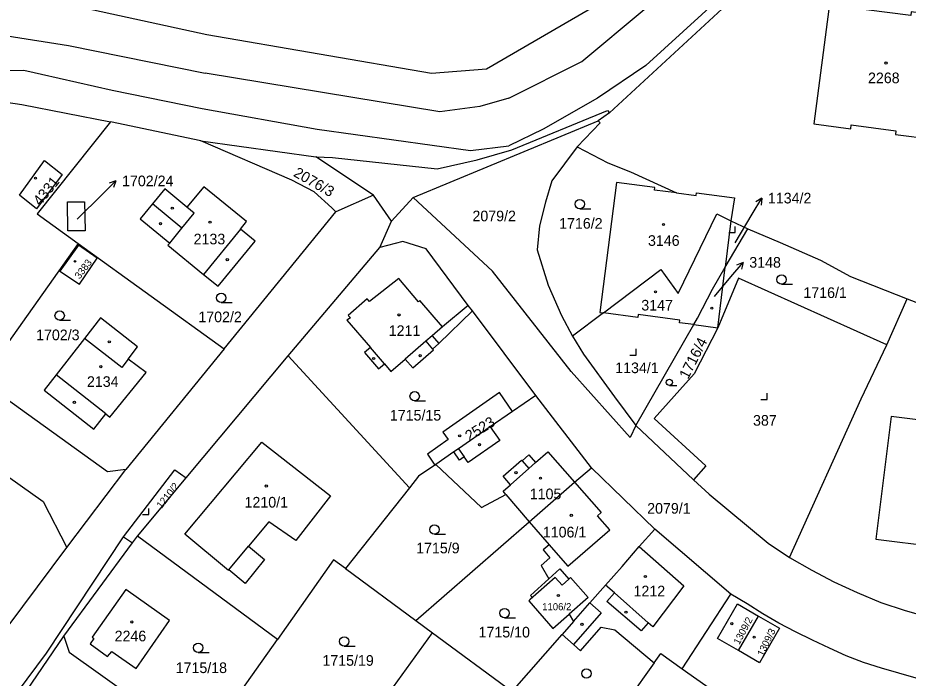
# Model space of a CAD drawing. Extents: x -679220 to -673243, y -1075091 to -1066557.
# Drawn here: x -676919.9 to -676777.4, y -1071850.3 to -1071744.6 of the extents above; entities that cross this region are included whole.
import ezdxf

# ---------------------------------------------------------------- set-up
doc = ezdxf.new("R2010")
doc.units = 0
for name, color, linetype in [('Hranice parcel', 7, 'Continuous'), ('Parcelní čísla', 7, 'Continuous'), ('Pop  PČ popisy', 7, 'Continuous'), ('Vnitřní kresba', 7, 'Continuous'), ('Značky budov', 7, 'Continuous'), ('Značky kultur', 7, 'Continuous')]:
    doc.layers.add(name, color=color, linetype=linetype)

msp = doc.modelspace()

# ---------------------------------------------------------------- linework, layer by layer
at = {"layer": 'Hranice parcel'}
for p, q in [((-676825.22, -1071759.86), (-676827.02, -1071761.13)), ((-676890.63, -1071764.33), (-676905.07, -1071761.28)), ((-676890.63, -1071764.33), (-676872.2, -1071766.9)), ((-676862.96, -1071773.03), (-676872.2, -1071766.9)), ((-676862.96, -1071773.03), (-676869.01, -1071775.7)), ((-676886.88, -1071797.62), (-676869.01, -1071775.7)), ((-676805.78, -1071777.13), (-676806.7, -1071784.54)), ((-676806.7, -1071784.54), (-676803.09, -1071778.39)), ((-676910.26, -1071780.74), (-676925.83, -1071802.72)), ((-676910.26, -1071780.74), (-676886.88, -1071797.62)), ((-676876.64, -1071798.73), (-676861.98, -1071781.43)), ((-676807.9, -1071794.25), (-676806.7, -1071784.54)), ((-676780.82, -1071796.99), (-676777.6, -1071789.6)), ((-676777.6, -1071789.6), (-676770.27, -1071792.52)), ((-676847.15, -1071791.53), (-676847.81, -1071790.66)), ((-676837, -1071805.08), (-676847.15, -1071791.53)), ((-676826.18, -1071791.87), (-676831.15, -1071795.62)), ((-676821, -1071809.91), (-676811.75, -1071793.75)), ((-676811.75, -1071793.75), (-676807.9, -1071794.25)), ((-676886.88, -1071797.62), (-676902.63, -1071816.93)), ((-676892.95, -1071818.26), (-676876.64, -1071798.73)), ((-676876.64, -1071798.73), (-676857.22, -1071819.86)), ((-676837, -1071805.08), (-676840.74, -1071807.66)), ((-676828.1, -1071816.65), (-676837, -1071805.08)), ((-676821, -1071809.91), (-676811.78, -1071818.6)), ((-676912.06, -1071829.42), (-676902.63, -1071816.93)), ((-676853.16, -1071816.22), (-676853, -1071816.11)), ((-676817.95, -1071826.46), (-676828.1, -1071816.65)), ((-676900.76, -1071827.6), (-676892.95, -1071818.26)), ((-676857.22, -1071819.86), (-676867.46, -1071832.8)), ((-676856.2, -1071841.09), (-676838.05, -1071825.29)), ((-676805.82, -1071836.89), (-676817.95, -1071826.46)), ((-676912.53, -1071843.62), (-676901.53, -1071828.65)), ((-676903, -1071827.69), (-676901.53, -1071828.65)), ((-676901.53, -1071828.65), (-676900.76, -1071827.6)), ((-676878.33, -1071844.13), (-676900.76, -1071827.6)), ((-676921.47, -1071842.02), (-676912.06, -1071829.42)), ((-676867.46, -1071832.8), (-676856.2, -1071841.09)), ((-676831.44, -1071834.22), (-676828.63, -1071837.43)), ((-676813.57, -1071848.81), (-676805.82, -1071836.89)), ((-676838.14, -1071837.94), (-676834.3, -1071842.37)), ((-676828.63, -1071837.43), (-676831.68, -1071840.08)), ((-676834.3, -1071842.37), (-676831.68, -1071840.08)), ((-676831.68, -1071840.08), (-676830.99, -1071841.28)), ((-676856.2, -1071841.09), (-676853.52, -1071843.07)), ((-676830.99, -1071841.28), (-676832.82, -1071843.36)), ((-676804.59, -1071845.91), (-676801.39, -1071840.38)), ((-676919.84, -1071854.28), (-676912.53, -1071843.62)), ((-676890.49, -1071861.28), (-676878.33, -1071844.13)), ((-676874.88, -1071872.43), (-676853.52, -1071843.07)), ((-676853.52, -1071843.07), (-676840.79, -1071852.44)), ((-676840.79, -1071852.44), (-676832.82, -1071843.36)), ((-676818.08, -1071847.87), (-676827.91, -1071861.55))]:
    msp.add_line(p, q, dxfattribs=at)
for points in [[(-676751.12, -1071692.06), (-676777.6, -1071716.31), (-676788.46, -1071725.85), (-676825.22, -1071759.86)], [(-677008.25, -1071788.41), (-676995.25, -1071771.16), (-676987.7, -1071761.27), (-676980.12, -1071752.62), (-676972.27, -1071748.26), (-676964.86, -1071744.84), (-676950.01, -1071743.35), (-676935.78, -1071742.14), (-676921.36, -1071742.37), (-676911.47, -1071742.59), (-676889.65, -1071747.32), (-676853.71, -1071753.48), (-676844.92, -1071752.82), (-676823.69, -1071740.46)], [(-676773.55, -1071764.09), (-676771, -1071744.47), (-676776.92, -1071743.7), (-676777, -1071744.29), (-676784.12, -1071743.37), (-676784.04, -1071742.77), (-676789.95, -1071742.01), (-676792.53, -1071761.62), (-676786.59, -1071762.39), (-676786.52, -1071761.79), (-676779.4, -1071762.72), (-676779.47, -1071763.32), (-676773.55, -1071764.09)], [(-676926.82, -1071757.39), (-676919.25, -1071758.51), (-676905.07, -1071761.28)], [(-676872.2, -1071766.9), (-676869.55, -1071767.02), (-676852.79, -1071768.83), (-676846.37, -1071767.4), (-676840.86, -1071765.76), (-676825.55, -1071759.5), (-676825.22, -1071759.86)], [(-676905.07, -1071761.28), (-676916.81, -1071776.01), (-676910.26, -1071780.74)], [(-676821, -1071809.91), (-676821.93, -1071811.81), (-676831.37, -1071801.24), (-676843.92, -1071785.19), (-676856.66, -1071773.41), (-676827.02, -1071761.13)], [(-676827.02, -1071761.13), (-676826.71, -1071761.46), (-676830.41, -1071765.32)], [(-676869.01, -1071775.7), (-676869.67, -1071775.03), (-676872.47, -1071772.52), (-676876.08, -1071770.65), (-676890.63, -1071764.33)], [(-676830.41, -1071765.32), (-676834.45, -1071770.74), (-676835.48, -1071774.13), (-676836.43, -1071777.94), (-676836.78, -1071781.79), (-676835.01, -1071787.45), (-676832.91, -1071792.27), (-676831.15, -1071795.62)], [(-676830.41, -1071765.32), (-676825.51, -1071767.83), (-676821.88, -1071769.29), (-676814.49, -1071772.68)], [(-676912.83, -1071769.72), (-676916.91, -1071775.2), (-676919.66, -1071773.02), (-676915.61, -1071767.47), (-676912.83, -1071769.72)], [(-676900.32, -1071776.84), (-676895.6, -1071780.69), (-676895.88, -1071781.04), (-676890.17, -1071785.7), (-676887.83, -1071787.61), (-676881.94, -1071780.39), (-676884.28, -1071778.48), (-676883.29, -1071777.25), (-676890.12, -1071771.67), (-676892.85, -1071774.94), (-676896.4, -1071772.04), (-676898.36, -1071774.44), (-676900.32, -1071776.84)], [(-676814.49, -1071772.68), (-676818.04, -1071772.22), (-676817.98, -1071771.78), (-676824.08, -1071770.98), (-676826.78, -1071791.79), (-676826.18, -1071791.87)], [(-676861.98, -1071781.43), (-676860.12, -1071777.17), (-676862.96, -1071773.03)], [(-676814.49, -1071772.68), (-676811.34, -1071773.09), (-676811.28, -1071772.64), (-676805.21, -1071773.43), (-676805.78, -1071777.13)], [(-676911.97, -1071774.12), (-676909.25, -1071774.08), (-676909.15, -1071778.76), (-676911.91, -1071778.74), (-676911.97, -1071774.12)], [(-676826.18, -1071791.87), (-676817, -1071784.94), (-676814.22, -1071788.75), (-676808.04, -1071776.02), (-676805.78, -1071777.13)], [(-676805.78, -1071777.13), (-676804.01, -1071778), (-676803.09, -1071778.39)], [(-676803.09, -1071778.39), (-676797.91, -1071780.61), (-676791.43, -1071783.43), (-676786.63, -1071786.04), (-676777.6, -1071789.6)], [(-676910.21, -1071781.01), (-676913.16, -1071785.17), (-676910.06, -1071787.26), (-676907.22, -1071783.1), (-676910.21, -1071781.01)], [(-676847.81, -1071790.66), (-676854.58, -1071781.62), (-676858.3, -1071780.47), (-676861.98, -1071781.43)], [(-676811.75, -1071793.75), (-676811.15, -1071792.73), (-676808.76, -1071788.06), (-676806.7, -1071784.54)], [(-676847.81, -1071790.66), (-676851.94, -1071794.09), (-676855.55, -1071789.89), (-676855.8, -1071790.1), (-676858.93, -1071786.38), (-676863.65, -1071790.02), (-676863.98, -1071789.63), (-676867.03, -1071792.27), (-676866.69, -1071792.66), (-676867.23, -1071793.04), (-676863.49, -1071797.42), (-676864.43, -1071798.22), (-676862.21, -1071800.84), (-676861.25, -1071800.03), (-676860.19, -1071801.27), (-676857.9, -1071799.28), (-676856.7, -1071800.66), (-676853.41, -1071797.79), (-676853.54, -1071797.67), (-676852.53, -1071796.79), (-676847.15, -1071791.53)], [(-676780.82, -1071796.99), (-676804.59, -1071786.32), (-676807.9, -1071794.25)], [(-676915.67, -1071804.21), (-676907.75, -1071810.48), (-676905.82, -1071808.04), (-676905.18, -1071808.55), (-676899.37, -1071801.42), (-676902.23, -1071799.27), (-676900.75, -1071797.32), (-676906.66, -1071792.68), (-676909.22, -1071795.96), (-676913.78, -1071801.79), (-676915.67, -1071804.21)], [(-676811.75, -1071793.75), (-676814, -1071793.46), (-676813.94, -1071793.01), (-676820.64, -1071792.13), (-676820.7, -1071792.58), (-676826.18, -1071791.87)], [(-676807.9, -1071794.25), (-676811.69, -1071801.6), (-676818.09, -1071808.75), (-676809.79, -1071816.32), (-676811.78, -1071818.6)], [(-676831.15, -1071795.62), (-676829.37, -1071798.47), (-676824.41, -1071805.3), (-676821, -1071809.91)], [(-676796.43, -1071831.02), (-676784.92, -1071805.6), (-676780.82, -1071796.99)], [(-676902.63, -1071816.93), (-676905.53, -1071817.31), (-676925.83, -1071802.72)], [(-676957.07, -1071816.5), (-676948.08, -1071803.91), (-676941.64, -1071803.78), (-676915.86, -1071822.06), (-676912.06, -1071829.42)], [(-676840.74, -1071807.66), (-676842.84, -1071804.63), (-676851.88, -1071810.97), (-676851.06, -1071812.14), (-676854.37, -1071814.46), (-676853.16, -1071816.22)], [(-676840.74, -1071807.66), (-676844.29, -1071810.11), (-676849.36, -1071813.6), (-676850.11, -1071814.12), (-676853, -1071816.11)], [(-676782.58, -1071828.1), (-676763.72, -1071830.45), (-676761.17, -1071810.81), (-676767.16, -1071810.06), (-676767.23, -1071810.66), (-676774.26, -1071809.78), (-676774.19, -1071809.19), (-676780.13, -1071808.45), (-676782.58, -1071828.1)], [(-676903, -1071827.69), (-676894.79, -1071816.98), (-676892.95, -1071818.26)], [(-676853.16, -1071816.22), (-676855.77, -1071818.02), (-676857.22, -1071819.86)], [(-676853, -1071816.11), (-676845.7, -1071823.03), (-676841.81, -1071820.94), (-676838.05, -1071825.29)], [(-676838.05, -1071825.29), (-676830.83, -1071818.96), (-676828.1, -1071816.65)], [(-676811.78, -1071818.6), (-676809.29, -1071820.87), (-676806.14, -1071823.5), (-676799.85, -1071828.71), (-676796.43, -1071831.02)], [(-676838.05, -1071825.29), (-676834.88, -1071828.97), (-676835.84, -1071829.78), (-676834.76, -1071831.05), (-676836.15, -1071832.28), (-676834.92, -1071834.42)], [(-676830.99, -1071841.28), (-676828.36, -1071838.28), (-676825.87, -1071835.43), (-676823.17, -1071832.44), (-676820.47, -1071829.26), (-676817.95, -1071826.46)], [(-677004.82, -1071960.24), (-676990.19, -1071940.38), (-676962.75, -1071908.83), (-676942.14, -1071882.34), (-676915.32, -1071846.3), (-676903, -1071827.69)], [(-676867.46, -1071832.8), (-676869.37, -1071831.39), (-676878.33, -1071844.13)], [(-676796.43, -1071831.02), (-676792.83, -1071833.03), (-676789.32, -1071834.89), (-676785.61, -1071836.61), (-676781.79, -1071838.2), (-676777.93, -1071839.51), (-676774.12, -1071840.58), (-676766.4, -1071842.71)], [(-676834.92, -1071834.42), (-676833.18, -1071832.83), (-676831.73, -1071834.47), (-676831.44, -1071834.22)], [(-676834.92, -1071834.42), (-676837.84, -1071837.09), (-676837.59, -1071837.37), (-676837.97, -1071837.72), (-676837.93, -1071837.76), (-676838.14, -1071837.94)], [(-676895.64, -1071841.11), (-676902.61, -1071836.16), (-676908.03, -1071843.78), (-676907.74, -1071843.99), (-676908.32, -1071844.81), (-676905.57, -1071846.87), (-676904.88, -1071846.04), (-676900.99, -1071848.76), (-676895.64, -1071841.11)], [(-676771.45, -1071853.79), (-676772.98, -1071851.21), (-676781.69, -1071848.73), (-676784.55, -1071847.83), (-676787.33, -1071846.73), (-676790.03, -1071845.53), (-676792.76, -1071844.24), (-676795.46, -1071842.89), (-676798.1, -1071841.51), (-676800.68, -1071840.01), (-676803.21, -1071838.43), (-676805.82, -1071836.89)], [(-676804.59, -1071845.91), (-676807.95, -1071843.96), (-676804.75, -1071838.43), (-676801.39, -1071840.38)], [(-676801.39, -1071840.38), (-676798.02, -1071842.33), (-676801.22, -1071847.86), (-676804.59, -1071845.91)], [(-676832.82, -1071843.36), (-676830.99, -1071844.96), (-676829.87, -1071845.95), (-676826.56, -1071842.18), (-676824.36, -1071842.61), (-676818.08, -1071847.87)], [(-676912.53, -1071843.62), (-676911.69, -1071846.16), (-676890.49, -1071861.28)], [(-676818.08, -1071847.87), (-676817.01, -1071846.38), (-676813.57, -1071848.81)], [(-676813.57, -1071848.81), (-676800.96, -1071857.74), (-676796.88, -1071860.63)]]:
    msp.add_lwpolyline(points, dxfattribs=at)
at = {"layer": 'Pop  PČ popisy'}
for p, q in [((-676906.35, -1071772.86), (-676904.23, -1071770.74)), ((-676904.23, -1071770.74), (-676905.29, -1071771.09)), ((-676904.23, -1071770.74), (-676904.58, -1071771.8)), ((-676910.39, -1071776.86), (-676906.35, -1071772.86)), ((-676802.39, -1071776.08), (-676800.84, -1071773.51)), ((-676800.84, -1071773.51), (-676801.79, -1071774.11)), ((-676800.84, -1071773.51), (-676800.93, -1071774.62)), ((-676805.1, -1071780.67), (-676802.39, -1071776.08)), ((-676805.78, -1071786.08), (-676803.85, -1071783.78)), ((-676803.85, -1071783.78), (-676804.88, -1071784.23)), ((-676803.85, -1071783.78), (-676804.11, -1071784.87)), ((-676808.42, -1071789.22), (-676805.78, -1071786.08))]:
    msp.add_line(p, q, dxfattribs=at)
at = {"layer": 'Vnitřní kresba'}
for p, q in [((-676752.15, -1071690.71), (-676819.39, -1071752.3)), ((-676829.64, -1071751.64), (-676819.69, -1071743.29)), ((-676921.61, -1071747.51), (-676911.77, -1071749.08)), ((-676911.77, -1071749.08), (-676889.94, -1071753.53)), ((-676841.34, -1071757.49), (-676829.64, -1071751.64)), ((-676947.84, -1071753.18), (-676918.92, -1071753.04)), ((-676918.92, -1071753.04), (-676904.83, -1071756.21)), ((-676819.39, -1071752.3), (-676827.13, -1071757.51)), ((-676852.36, -1071759.69), (-676889.94, -1071753.53)), ((-676904.83, -1071756.21), (-676890.39, -1071759.16)), ((-676845.96, -1071758.84), (-676852.36, -1071759.69)), ((-676841.34, -1071757.49), (-676845.96, -1071758.84)), ((-676827.13, -1071757.51), (-676835.85, -1071762.49)), ((-676890.39, -1071759.16), (-676871.99, -1071762.48)), ((-676871.99, -1071762.48), (-676847.45, -1071765.89)), ((-676835.85, -1071762.49), (-676841.32, -1071765.16)), ((-676847.45, -1071765.89), (-676841.32, -1071765.16)), ((-676893.64, -1071778.29), (-676898.36, -1071774.44)), ((-676860.12, -1071777.17), (-676856.66, -1071773.41)), ((-676893.64, -1071778.29), (-676891.68, -1071775.89)), ((-676891.68, -1071775.89), (-676892.85, -1071774.94)), ((-676895.6, -1071780.69), (-676893.64, -1071778.29)), ((-676884.28, -1071778.48), (-676890.17, -1071785.7)), ((-676851.94, -1071794.09), (-676853.61, -1071795.54)), ((-676853.61, -1071795.54), (-676854.61, -1071796.41)), ((-676853.61, -1071795.54), (-676852.53, -1071796.79)), ((-676903.26, -1071800.63), (-676909.22, -1071795.96)), ((-676854.61, -1071796.41), (-676857.9, -1071799.28)), ((-676854.61, -1071796.41), (-676853.54, -1071797.67)), ((-676861.25, -1071800.03), (-676863.49, -1071797.42)), ((-676902.23, -1071799.27), (-676903.26, -1071800.63)), ((-676905.82, -1071808.04), (-676913.78, -1071801.79)), ((-676844.29, -1071810.11), (-676842.78, -1071812.3)), ((-676893.17, -1071827.29), (-676880.88, -1071812.56)), ((-676880.88, -1071812.56), (-676869.86, -1071821.13)), ((-676842.78, -1071812.3), (-676847.85, -1071815.8)), ((-676849.2, -1071815.44), (-676850.11, -1071814.12)), ((-676849.36, -1071813.6), (-676848.45, -1071814.92)), ((-676837.05, -1071815.82), (-676835.09, -1071814.09)), ((-676835.09, -1071814.09), (-676830.83, -1071818.96)), ((-676848.45, -1071814.92), (-676849.2, -1071815.44)), ((-676847.85, -1071815.8), (-676848.45, -1071814.92)), ((-676842.24, -1071818), (-676839.3, -1071815.44)), ((-676839.3, -1071815.44), (-676839.22, -1071815.53)), ((-676839.22, -1071815.53), (-676838.14, -1071814.58)), ((-676839.22, -1071815.53), (-676838.12, -1071816.77)), ((-676838.14, -1071814.58), (-676837.05, -1071815.82)), ((-676838.12, -1071816.77), (-676837.05, -1071815.82)), ((-676838.12, -1071816.77), (-676841.06, -1071819.37)), ((-676841.06, -1071819.37), (-676842.24, -1071818)), ((-676842.26, -1071820.41), (-676841.06, -1071819.37)), ((-676830.83, -1071818.96), (-676826.56, -1071823.83)), ((-676869.86, -1071821.13), (-676875.43, -1071828.29)), ((-676841.81, -1071820.94), (-676842.26, -1071820.41)), ((-676827.12, -1071824.34), (-676826.56, -1071823.83)), ((-676825.19, -1071826.58), (-676827.12, -1071824.34)), ((-676879.73, -1071825.29), (-676882.98, -1071829.19)), ((-676875.43, -1071828.29), (-676879.73, -1071825.29)), ((-676831.88, -1071832.38), (-676825.19, -1071826.58)), ((-676886.2, -1071833.09), (-676893.17, -1071827.29)), ((-676886.13, -1071832.97), (-676882.98, -1071829.19)), ((-676882.98, -1071829.19), (-676880.43, -1071831.31)), ((-676834.88, -1071828.97), (-676833.81, -1071830.21)), ((-676820.47, -1071829.26), (-676813.3, -1071835.57)), ((-676880.43, -1071831.31), (-676883.51, -1071835.15)), ((-676833.81, -1071830.21), (-676831.88, -1071832.38)), ((-676886.13, -1071832.97), (-676886.2, -1071833.09)), ((-676883.51, -1071835.15), (-676886.13, -1071832.97)), ((-676833.89, -1071834.21), (-676837.93, -1071837.76)), ((-676832.81, -1071835.42), (-676833.89, -1071834.21)), ((-676831.73, -1071834.47), (-676832.81, -1071835.42)), ((-676824.44, -1071836.67), (-676825.87, -1071835.43)), ((-676813.3, -1071835.57), (-676818.26, -1071842.12)), ((-676825.64, -1071838.04), (-676824.44, -1071836.67)), ((-676824.44, -1071836.67), (-676819.01, -1071841.46)), ((-676828.36, -1071838.28), (-676826.53, -1071839.88)), ((-676820.16, -1071842.76), (-676825.64, -1071838.04)), ((-676826.53, -1071839.88), (-676830.99, -1071844.96)), ((-676819.01, -1071841.46), (-676820.16, -1071842.76)), ((-676818.26, -1071842.12), (-676819.01, -1071841.46))]:
    msp.add_line(p, q, dxfattribs=at)
at = {"layer": 'Značky budov'}
for centre, radius in [((-676780.97, -1071751.89), 0.175), ((-676917.08, -1071770.31), 0.175), ((-676895.19, -1071775.11), 0.175), ((-676889.14, -1071777.35), 0.175), ((-676897.07, -1071777.58), 0.175), ((-676816.58, -1071777.73), 0.175), ((-676910.75, -1071783.62), 0.117), ((-676886.38, -1071783.34), 0.175), ((-676817.86, -1071788.49), 0.175), ((-676808.85, -1071791.11), 0.175), ((-676858.9, -1071792.19), 0.175), ((-676905.27, -1071796.51), 0.175), ((-676855.52, -1071798.72), 0.175), ((-676862.97, -1071799.17), 0.175), ((-676906.62, -1071800.48), 0.175), ((-676910.85, -1071806.18), 0.175), ((-676849.19, -1071811.55), 0.175), ((-676846.02, -1071812.96), 0.175), ((-676840.19, -1071817.45), 0.175), ((-676836.26, -1071818.32), 0.175), ((-676880.15, -1071819.58), 0.175), ((-676831.34, -1071824.28), 0.175), ((-676819.48, -1071834.06), 0.175), ((-676833.4, -1071837.1), 0.175), ((-676822.59, -1071839.76), 0.175), ((-676901.66, -1071841.33), 0.175), ((-676805.64, -1071841.61), 0.175), ((-676829.62, -1071841.72), 0.175), ((-676802.07, -1071843.77), 0.175)]:
    msp.add_circle(centre, radius, dxfattribs=at)
at = {"layer": 'Značky kultur'}
for p, q in [((-676829.97, -1071775.21), (-676828.22, -1071775.21)), ((-676805.13, -1071779.02), (-676805.13, -1071778.02)), ((-676806.13, -1071779.02), (-676805.13, -1071779.02)), ((-676797.68, -1071787.28), (-676795.93, -1071787.28)), ((-676887.36, -1071790.21), (-676885.61, -1071790.21)), ((-676913.21, -1071793.04), (-676911.46, -1071793.04)), ((-676821.94, -1071798.64), (-676820.94, -1071798.64)), ((-676820.94, -1071798.64), (-676820.94, -1071797.64)), ((-676815.62, -1071803.49), (-676814.45, -1071803.49)), ((-676800.98, -1071805.71), (-676799.98, -1071805.71)), ((-676799.98, -1071805.71), (-676799.98, -1071804.71)), ((-676856.4, -1071805.95), (-676854.65, -1071805.95)), ((-676899.94, -1071824.15), (-676898.94, -1071824.15)), ((-676898.94, -1071824.15), (-676898.94, -1071823.15)), ((-676853.24, -1071827.3), (-676851.49, -1071827.3)), ((-676842.01, -1071840.65), (-676840.26, -1071840.65)), ((-676867.66, -1071845.2), (-676865.91, -1071845.2)), ((-676891.03, -1071846.21), (-676889.28, -1071846.21))]:
    msp.add_line(p, q, dxfattribs=at)
for centre, radius in [((-676829.97, -1071774.46), 0.75), ((-676797.68, -1071786.53), 0.75), ((-676887.36, -1071789.46), 0.75), ((-676913.21, -1071792.29), 0.75), ((-676815.63, -1071802.99), 0.502), ((-676856.4, -1071805.2), 0.75), ((-676853.24, -1071826.55), 0.75), ((-676842.01, -1071839.9), 0.75), ((-676867.66, -1071844.45), 0.75), ((-676891.03, -1071845.46), 0.75), ((-676828.91, -1071849.58), 0.75)]:
    msp.add_circle(centre, radius, dxfattribs=at)

# ---------------------------------------------------------------- texts
at = {"layer": 'Parcelní čísla'}
for s, height, p in [('2268', 1.7, (-676783.85, -1071755.11)), ('1702/24', 1.7, (-676903.22, -1071771.6)), ('1134/2', 1.7, (-676799.87, -1071774.35)), ('2079/2', 1.7, (-676847.15, -1071777.21)), ('1716/2', 1.7, (-676833.28, -1071778.39)), ('2133', 1.7, (-676891.77, -1071780.9)), ('3146', 1.7, (-676819.06, -1071781.14)), ('3148', 1.7, (-676802.85, -1071784.63)), ('1716/1', 1.7, (-676794.19, -1071789.48)), ('3147', 1.7, (-676820.13, -1071791.49)), ('1702/2', 1.7, (-676891.01, -1071793.36)), ('1702/3', 1.7, (-676916.98, -1071796.24)), ('1211', 1.7, (-676860.55, -1071795.56)), ('1134/1', 1.7, (-676824.3, -1071801.51)), ('2134', 1.7, (-676908.84, -1071803.71)), ('1715/15', 1.7, (-676860.37, -1071809.1)), ('387', 1.7, (-676802.25, -1071809.92)), ('1105', 1.7, (-676837.98, -1071821.69)), ('1210/1', 1.7, (-676883.62, -1071823.02)), ('2079/1', 1.7, (-676819.19, -1071824)), ('1106/1', 1.7, (-676835.89, -1071827.8)), ('1715/9', 1.7, (-676856.16, -1071830.35)), ('1212', 1.7, (-676821.37, -1071837.23)), ('1106/2', 1.14, (-676835.99, -1071839.46)), ('2246', 1.7, (-676904.41, -1071844.43)), ('1715/10', 1.7, (-676846.17, -1071843.81)), ('1715/19', 1.7, (-676871.16, -1071848.34)), ('1715/18', 1.7, (-676894.64, -1071849.51))]:
    msp.add_text(s, height=height, dxfattribs=at).set_placement(p)
for s, height, rotation, p in [('2076/3', 1.7, 330, (-676875.92, -1071769.91)), ('4331', 1.7, 51, (-676916.31, -1071774.84)), ('3383', 1.14, 53, (-676910, -1071786.54)), ('1716/4', 1.7, 63, (-676812.65, -1071802.59)), ('2523', 1.7, 32, (-676847.65, -1071812.46)), ('1210/2', 1.14, 52, (-676896.91, -1071823.27)), ('1309/2', 1.14, 62, (-676804.45, -1071845.05)), ('1309/3', 1.14, 64, (-676800.63, -1071846.91))]:
    msp.add_text(s, height=height, rotation=rotation, dxfattribs=at).set_placement(p)

doc.saveas('drawing.dxf')
